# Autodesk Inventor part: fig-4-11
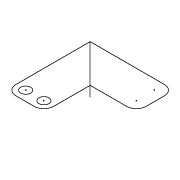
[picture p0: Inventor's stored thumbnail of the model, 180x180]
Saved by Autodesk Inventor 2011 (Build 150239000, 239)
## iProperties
Created: 2005-02
Part Number: fig-4-11
Document SubType Name: Modeling
Designer: CADCIM
Manufacturer: Standard
Standards Organization: Custom
Density: 1 g/cm^3
Author: CADCIM
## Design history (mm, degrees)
sketch "Sketch1"
  geometry: L1 (5.141, 24.979)-(-32.827, 24.979); L2 (-32.827, 24.979)-(-32.827, -12.989); L3 (-27.827, -17.989)-(-18.492, -17.989); L4 (-13.492, -12.989)-(-13.492, 5.644); L5 (-13.492, 5.644)-(5.141, 5.644); L6 (10.141, 10.644)-(10.141, 19.979); L7 (-32.827, 24.979)-(-8.203, 0.354); C1 r 2.58 at (-27.827, -12.989); C2 r 2.58 at (-18.492, -12.989); A1 r 5 centre (-27.827, -12.989) between (-32.827, -12.989) and (-27.827, -17.989); A2 r 5 centre (-18.492, -12.989) between (-18.492, -17.989) and (-13.492, -12.989); A3 r 5 centre (5.141, 10.644) between (5.141, 5.644) and (10.141, 10.644); A4 r 5 centre (5.141, 19.979) between (10.141, 19.979) and (5.141, 24.979)
  constraints: 14 end point, 8 point on circle, 8 tangent, 6 centre point, 4 equal radius, 4 parallel, 3 perpendicular, 2 coincident, 1 horizontal, 1 point on line
